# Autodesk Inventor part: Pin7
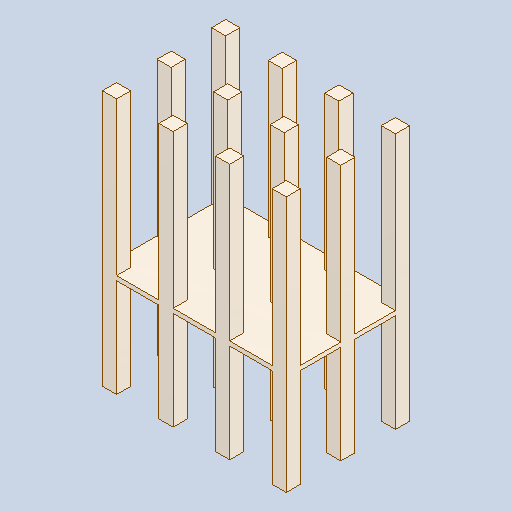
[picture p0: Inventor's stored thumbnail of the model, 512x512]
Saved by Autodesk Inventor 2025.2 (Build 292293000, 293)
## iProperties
Created: 2025-04
Part Number: Pin7
Material: Generic
Description: PART--DESC
Document SubType Name: Modeling
Designer: BennF
Density: 1 g/cm^3
Appearance: Default
Author: BennF
Revision Number: NONE
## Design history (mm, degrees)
feature "Solid"
body "Solid1"
